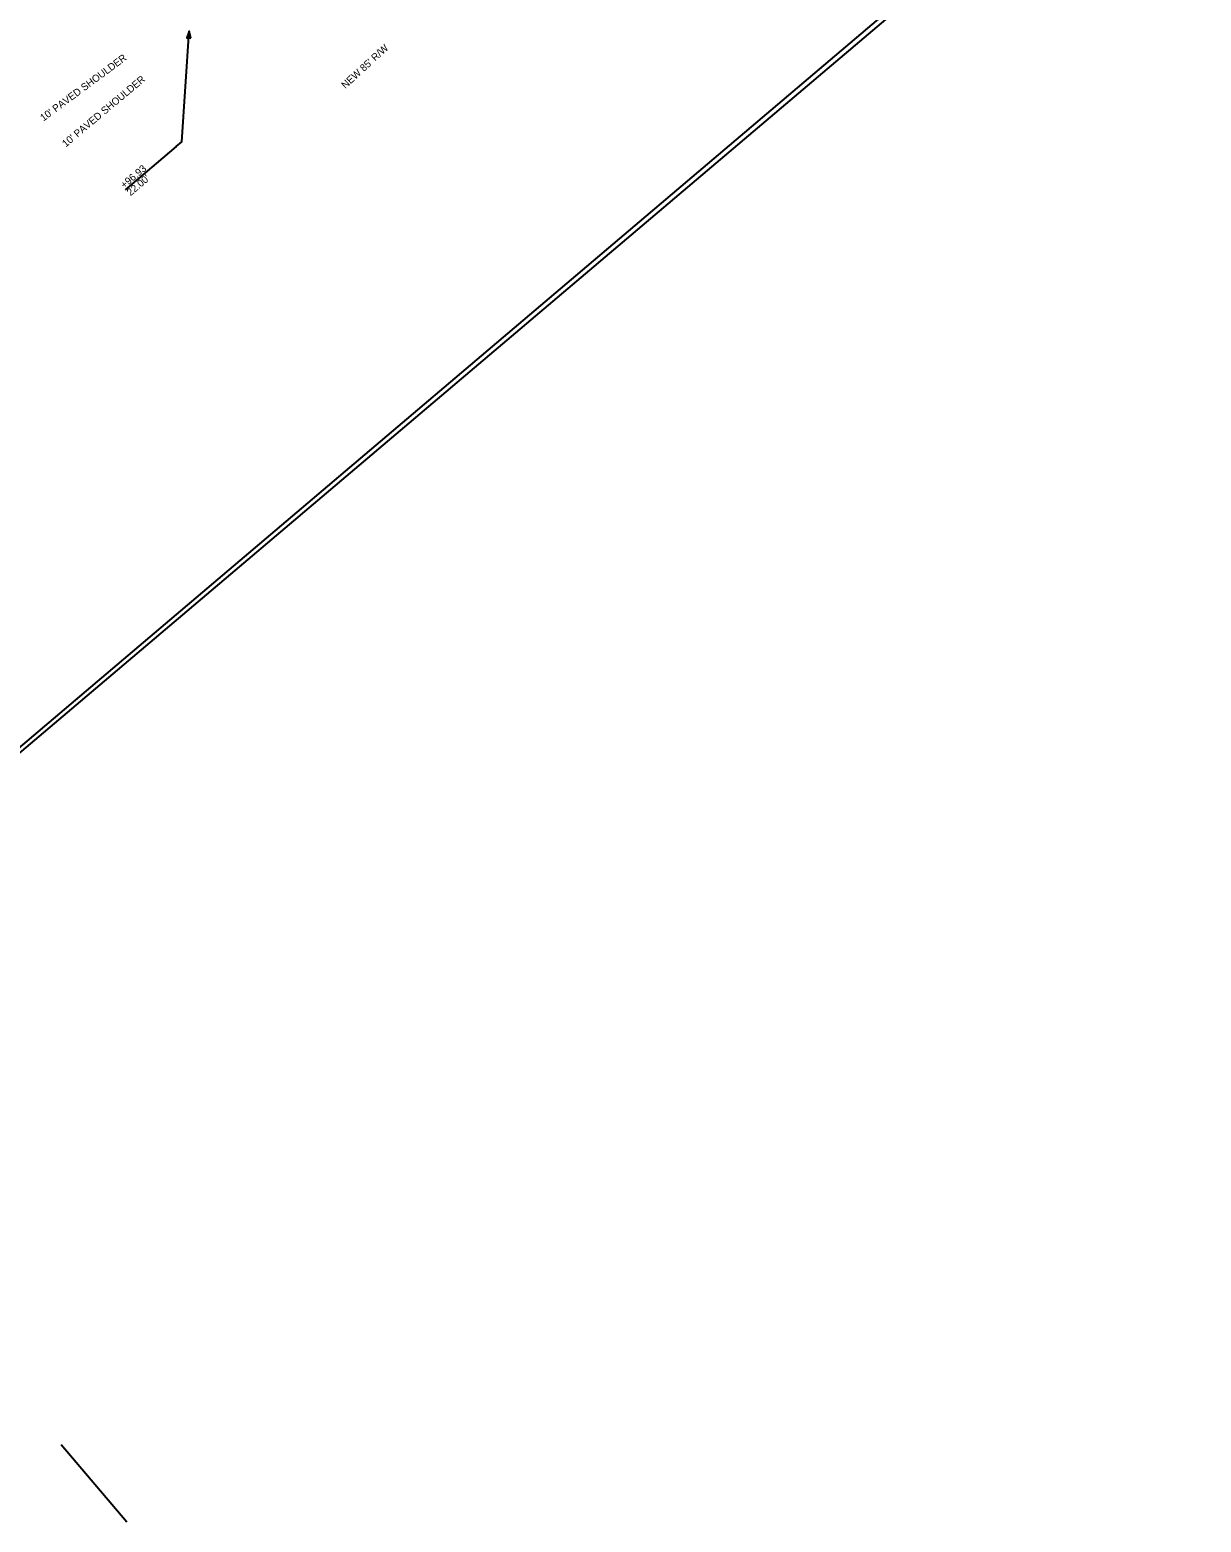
# Model space of a CAD drawing. Extents: x 1613433 to 1615331, y 1095338 to 1097615.
# Drawn here: x 1614358 to 1615329, y 1095338 to 1096576 of the extents above; entities that cross this region are included whole.
import ezdxf

# ---------------------------------------------------------------- set-up
doc = ezdxf.new("R2010")
doc.units = 0
for name, color, linetype in [('RD_EX_DR_Pipe', 7, 'Continuous'), ('RD_EX_GuardRail', 7, 'Continuous'), ('RD_PD_RW_TX', 7, 'Continuous'), ('RD_SHT_UT_TX_PREL', 7, 'Continuous')]:
    doc.layers.add(name, color=color, linetype=linetype)

msp = doc.modelspace()

# ---------------------------------------------------------------- linework, layer by layer
at = {"layer": 'RD_EX_DR_Pipe'}
msp.add_lwpolyline([(1613636.5, 1096424.5), (1613794.6, 1096211.8), (1613781.7, 1096202.2), (1613853.4, 1096105.7), (1613849.9, 1096103.1), (1613959.1, 1095956.1), (1614080.2, 1095752.7), (1615305.3, 1096791.9), (1615113.5, 1096968), (1614971.2, 1097080.2), (1614985.2, 1097098.2), (1614915.3, 1097153.9), (1614938.7, 1097183.2), (1614788.8, 1097308.4), (1614642.5, 1097430.7), (1614558.9, 1097359.3), (1614537.2, 1097384.7), (1613565.8, 1096563.6)], close=True, dxfattribs=at)
msp.add_lwpolyline([(1613636.5, 1096424.5), (1613794.6, 1096211.8), (1613781.7, 1096202.2), (1613853.4, 1096105.7), (1613849.9, 1096103.1), (1613959.1, 1095956.1), (1614080.2, 1095752.7), (1615305.3, 1096791.9), (1615113.5, 1096968), (1614971.2, 1097080.2), (1614985.2, 1097098.2), (1614915.3, 1097153.9), (1614938.7, 1097183.2), (1614788.8, 1097308.4), (1614642.5, 1097430.7), (1614558.9, 1097359.3), (1614537.2, 1097384.7), (1613565.8, 1096563.6)], close=True, dxfattribs=at)
at = {"layer": 'RD_EX_GuardRail'}
msp.add_lwpolyline([(1613432.5, 1096453.7), (1614710.7, 1097536.3), (1615328.9, 1096806.4), (1614050.7, 1095723.8)], close=True, dxfattribs=at)
at = {"layer": 'RD_SHT_UT_TX_PREL'}
for p, q in [((1614479, 1096478.9), (1614436.5, 1096443)), ((1614437.9, 1095338.1), (1614383.5, 1095402.3))]:
    msp.add_line(p, q, dxfattribs=at)
msp.add_lwpolyline([(1614479, 1096478.9), (1614483.7, 1096482.9), (1614489.8, 1096574.7)], dxfattribs=at)
msp.add_lwpolyline([(1614491, 1096568.8), (1614489.8, 1096574.7), (1614487.9, 1096569)], close=True, dxfattribs=at)

# ---------------------------------------------------------------- texts
at = {"layer": 'RD_PD_RW_TX'}
msp.add_text("NEW 85' R/W", height=6, rotation=42.5756, dxfattribs=at).set_placement((1614619.2, 1096526.6))
at = {"layer": 'RD_SHT_UT_TX_PREL'}
for s, rotation, p in [("10' PAVED SHOULDER", 36.624, (1614368.9, 1096499.6)), ("10' PAVED SHOULDER", 39.9775, (1614387.4, 1096478.1)), ('+96.93', 40.265, (1614435.9, 1096443.8)), ("22.00'", 40.265, (1614441.1, 1096437.7))]:
    msp.add_text(s, height=6, rotation=rotation, dxfattribs=at).set_placement(p)

doc.saveas('drawing.dxf')
